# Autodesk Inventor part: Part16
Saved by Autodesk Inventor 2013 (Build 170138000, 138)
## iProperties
Created: 2012-07
Part Number: Part16
Material: Generic
Document SubType Name: Modeling
Designer: Paul
Density: 1 g/cm^3
Author: Paul
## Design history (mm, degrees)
node "User Library-Arduino Mega.SAT1"
body "Solid1"
node "Base1"
